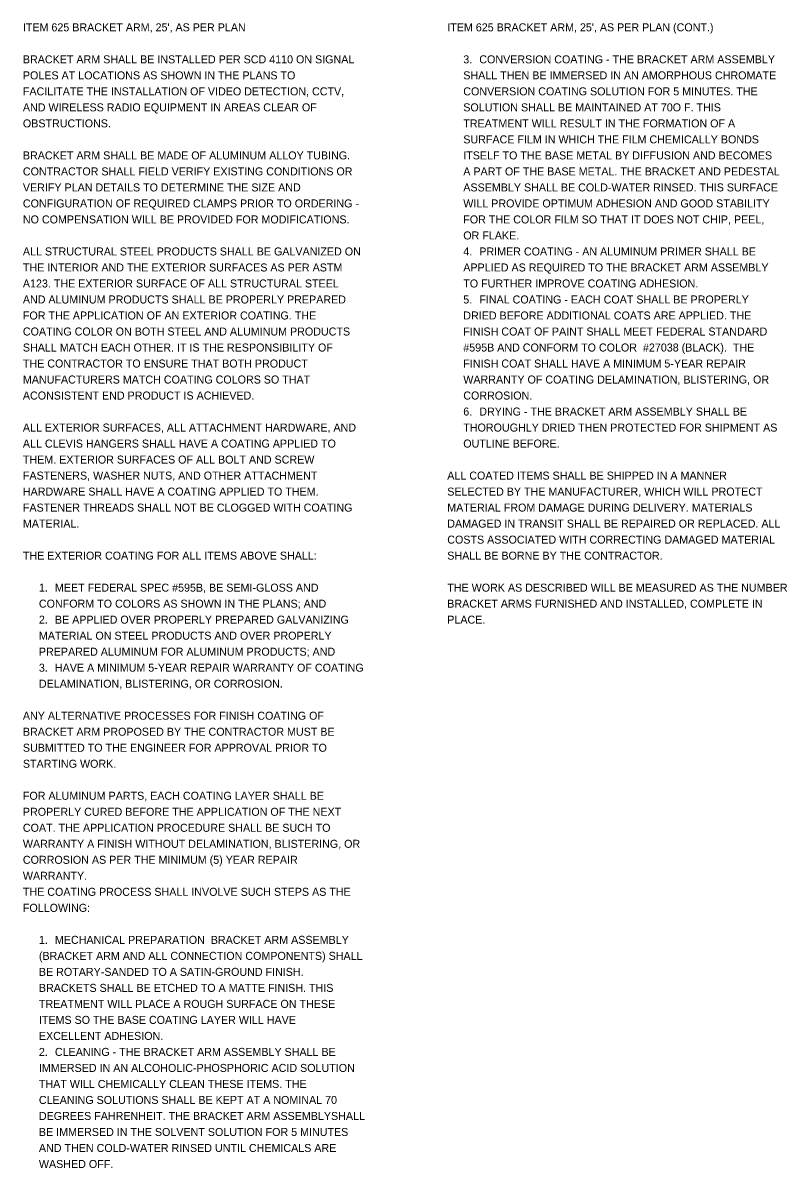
# Model space of a CAD drawing. Extents: x -25.6 to 66.7, y -23.1 to 37.2.
# Drawn here: x 9.81 to 23.18, y 17.02 to 37.05 of the extents above; entities that cross this region are included whole.
import ezdxf

# ---------------------------------------------------------------- set-up
doc = ezdxf.new("R2010")
doc.units = 0
doc.layers.add('SH_Text', color=7, linetype='Continuous')

msp = doc.modelspace()

# ---------------------------------------------------------------- texts
at = {"layer": 'SH_Text'}
for s, p in [("ITEM 625 BRACKET ARM, 25', AS PER PLAN ", (9.814, 36.902)), ("ITEM 625 BRACKET ARM, 25', AS PER PLAN (CONT.)", (17.234, 36.902)), ('BRACKET ARM SHALL BE INSTALLED PER SCD 4110 ON SIGNAL ', (9.814, 36.342)), ('3.', (17.514, 36.342)), ('CONVERSION COATING - THE BRACKET ARM ASSEMBLY ', (17.794, 36.342)), ('POLES AT LOCATIONS AS SHOWN IN THE PLANS TO ', (9.814, 36.062)), ('SHALL THEN BE IMMERSED IN AN AMORPHOUS CHROMATE ', (17.514, 36.062)), ('FACILITATE THE INSTALLATION OF VIDEO DETECTION, CCTV, ', (9.814, 35.782)), ('CONVERSION COATING SOLUTION FOR 5 MINUTES. THE ', (17.514, 35.782)), ('AND WIRELESS RADIO EQUIPMENT IN AREAS CLEAR OF ', (9.814, 35.502)), ('SOLUTION SHALL BE MAINTAINED AT 70O F. THIS ', (17.514, 35.502)), ('OBSTRUCTIONS. ', (9.814, 35.222)), ('TREATMENT WILL RESULT IN THE FORMATION OF A ', (17.514, 35.222)), ('SURFACE FILM IN WHICH THE FILM CHEMICALLY BONDS ', (17.514, 34.942)), ('BRACKET ARM SHALL BE MADE OF ALUMINUM ALLOY TUBING. ', (9.814, 34.662)), ('ITSELF TO THE BASE METAL BY DIFFUSION AND BECOMES ', (17.514, 34.662)), ('CONTRACTOR SHALL FIELD VERIFY EXISTING CONDITIONS OR ', (9.814, 34.382)), ('A PART OF THE BASE METAL. THE BRACKET AND PEDESTAL ', (17.514, 34.382)), ('VERIFY PLAN DETAILS TO DETERMINE THE SIZE AND ', (9.814, 34.102)), ('ASSEMBLY SHALL BE COLD-WATER RINSED. THIS SURFACE ', (17.514, 34.102)), ('CONFIGURATION OF REQUIRED CLAMPS PRIOR TO ORDERING - ', (9.814, 33.822)), ('WILL PROVIDE OPTIMUM ADHESION AND GOOD STABILITY ', (17.514, 33.822)), ('NO COMPENSATION WILL BE PROVIDED FOR MODIFICATIONS.', (9.814, 33.542)), ('FOR THE COLOR FILM SO THAT IT DOES NOT CHIP, PEEL, ', (17.514, 33.542)), ('OR FLAKE.', (17.514, 33.262)), ('ALL STRUCTURAL STEEL PRODUCTS SHALL BE GALVANIZED ON ', (9.814, 32.982)), ('4.', (17.514, 32.982)), ('PRIMER COATING - AN ALUMINUM PRIMER SHALL BE ', (17.794, 32.982)), ('THE INTERIOR AND THE EXTERIOR SURFACES AS PER ASTM ', (9.814, 32.702)), ('APPLIED AS REQUIRED TO THE BRACKET ARM ASSEMBLY ', (17.514, 32.702)), ('A123. THE EXTERIOR SURFACE OF ALL STRUCTURAL STEEL ', (9.814, 32.422)), ('TO FURTHER IMPROVE COATING ADHESION.', (17.514, 32.422)), ('AND ALUMINUM PRODUCTS SHALL BE PROPERLY PREPARED ', (9.814, 32.142)), ('5.', (17.514, 32.142)), ('FINAL COATING - EACH COAT SHALL BE PROPERLY ', (17.794, 32.142)), ('FOR THE APPLICATION OF AN EXTERIOR COATING. THE ', (9.814, 31.862)), ('DRIED BEFORE ADDITIONAL COATS ARE APPLIED. THE ', (17.514, 31.862)), ('COATING COLOR ON BOTH STEEL AND ALUMINUM PRODUCTS ', (9.814, 31.582)), ('FINISH COAT OF PAINT SHALL MEET FEDERAL STANDARD ', (17.514, 31.582)), ('#595B AND CONFORM TO COLOR  #27038 (BLACK).  THE ', (17.514, 31.302)), ('SHALL MATCH EACH OTHER. IT IS THE RESPONSIBILITY OF ', (9.814, 31.302)), ('THE CONTRACTOR TO ENSURE THAT BOTH PRODUCT ', (9.814, 31.022)), ('FINISH COAT SHALL HAVE A MINIMUM 5-YEAR REPAIR ', (17.514, 31.022)), ('MANUFACTURERS MATCH COATING COLORS SO THAT ', (9.814, 30.742)), ('WARRANTY OF COATING DELAMINATION, BLISTERING, OR ', (17.514, 30.742)), ('ACONSISTENT END PRODUCT IS ACHIEVED.', (9.814, 30.462)), ('CORROSION.', (17.514, 30.462)), ('6.', (17.514, 30.182)), ('DRYING - THE BRACKET ARM ASSEMBLY SHALL BE ', (17.794, 30.182)), ('ALL EXTERIOR SURFACES, ALL ATTACHMENT HARDWARE, AND ', (9.814, 29.902)), ('THOROUGHLY DRIED THEN PROTECTED FOR SHIPMENT AS ', (17.514, 29.902)), ('ALL CLEVIS HANGERS SHALL HAVE A COATING APPLIED TO ', (9.814, 29.622)), ('OUTLINE BEFORE.', (17.514, 29.622)), ('THEM. EXTERIOR SURFACES OF ALL BOLT AND SCREW ', (9.814, 29.342)), ('FASTENERS, WASHER NUTS, AND OTHER ATTACHMENT ', (9.814, 29.062)), ('ALL COATED ITEMS SHALL BE SHIPPED IN A MANNER ', (17.234, 29.062)), ('HARDWARE SHALL HAVE A COATING APPLIED TO THEM. ', (9.814, 28.782)), ('SELECTED BY THE MANUFACTURER, WHICH WILL PROTECT ', (17.234, 28.782)), ('FASTENER THREADS SHALL NOT BE CLOGGED WITH COATING ', (9.814, 28.502)), ('MATERIAL FROM DAMAGE DURING DELIVERY. MATERIALS ', (17.234, 28.502)), ('MATERIAL.', (9.814, 28.222)), ('DAMAGED IN TRANSIT SHALL BE REPAIRED OR REPLACED. ALL ', (17.234, 28.222)), ('COSTS ASSOCIATED WITH CORRECTING DAMAGED MATERIAL ', (17.234, 27.942)), ('THE EXTERIOR COATING FOR ALL ITEMS ABOVE SHALL:', (9.814, 27.662)), ('SHALL BE BORNE BY THE CONTRACTOR.', (17.234, 27.662)), ('1.', (10.094, 27.102)), ('MEET FEDERAL SPEC #595B, BE SEMI-GLOSS AND ', (10.374, 27.102)), ('THE WORK AS DESCRIBED WILL BE MEASURED AS THE NUMBER ', (17.234, 27.102)), ('CONFORM TO COLORS AS SHOWN IN THE PLANS; AND', (10.094, 26.822)), ('BRACKET ARMS FURNISHED AND INSTALLED, COMPLETE IN ', (17.234, 26.822)), ('2.', (10.094, 26.542)), ('BE APPLIED OVER PROPERLY PREPARED GALVANIZING ', (10.374, 26.542)), ('PLACE.', (17.234, 26.542)), ('MATERIAL ON STEEL PRODUCTS AND OVER PROPERLY ', (10.094, 26.262)), ('PREPARED ALUMINUM FOR ALUMINUM PRODUCTS; AND', (10.094, 25.982)), ('3.', (10.094, 25.702)), ('HAVE A MINIMUM 5-YEAR REPAIR WARRANTY OF COATING ', (10.374, 25.702)), ('DELAMINATION, BLISTERING, OR CORROSION. ', (10.094, 25.422)), ('ANY ALTERNATIVE PROCESSES FOR FINISH COATING OF ', (9.814, 24.862)), ('BRACKET ARM PROPOSED BY THE CONTRACTOR MUST BE ', (9.814, 24.582)), ('SUBMITTED TO THE ENGINEER FOR APPROVAL PRIOR TO ', (9.814, 24.302)), ('STARTING WORK.', (9.814, 24.022)), ('FOR ALUMINUM PARTS, EACH COATING LAYER SHALL BE ', (9.814, 23.462)), ('PROPERLY CURED BEFORE THE APPLICATION OF THE NEXT ', (9.814, 23.182)), ('COAT. THE APPLICATION PROCEDURE SHALL BE SUCH TO ', (9.814, 22.902)), ('WARRANTY A FINISH WITHOUT DELAMINATION, BLISTERING, OR ', (9.814, 22.622)), ('CORROSION AS PER THE MINIMUM (5) YEAR REPAIR ', (9.814, 22.342)), ('WARRANTY.', (9.814, 22.062)), ('THE COATING PROCESS SHALL INVOLVE SUCH STEPS AS THE ', (9.814, 21.782)), ('FOLLOWING:', (9.814, 21.502)), ('1.', (10.094, 20.942)), ('MECHANICAL PREPARATION  BRACKET ARM ASSEMBLY ', (10.374, 20.942)), ('(BRACKET ARM AND ALL CONNECTION COMPONENTS) SHALL ', (10.094, 20.662)), ('BE ROTARY-SANDED TO A SATIN-GROUND FINISH. ', (10.094, 20.382)), ('BRACKETS SHALL BE ETCHED TO A MATTE FINISH. THIS ', (10.094, 20.102)), ('TREATMENT WILL PLACE A ROUGH SURFACE ON THESE ', (10.094, 19.822)), ('ITEMS SO THE BASE COATING LAYER WILL HAVE ', (10.094, 19.542)), ('EXCELLENT ADHESION.', (10.094, 19.262)), ('2.', (10.094, 18.982)), ('CLEANING - THE BRACKET ARM ASSEMBLY SHALL BE ', (10.374, 18.982)), ('IMMERSED IN AN ALCOHOLIC-PHOSPHORIC ACID SOLUTION ', (10.094, 18.702)), ('THAT WILL CHEMICALLY CLEAN THESE ITEMS. THE ', (10.094, 18.422)), ('CLEANING SOLUTIONS SHALL BE KEPT AT A NOMINAL 70 ', (10.094, 18.142)), ('DEGREES FAHRENHEIT. THE BRACKET ARM ASSEMBLYSHALL ', (10.094, 17.862)), ('BE IMMERSED IN THE SOLVENT SOLUTION FOR 5 MINUTES ', (10.094, 17.582)), ('AND THEN COLD-WATER RINSED UNTIL CHEMICALS ARE ', (10.094, 17.302)), ('WASHED OFF.', (10.094, 17.022))]:
    msp.add_text(s, height=0.14, dxfattribs=at).set_placement(p)

doc.saveas('drawing.dxf')
